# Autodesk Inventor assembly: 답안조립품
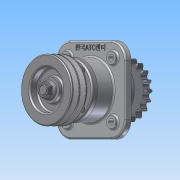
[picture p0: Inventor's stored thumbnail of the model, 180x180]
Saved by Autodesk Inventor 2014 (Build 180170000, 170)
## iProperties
Created: 2015-09
Part Number: 답안조립품
Document SubType Name: Assembly
Designer: study
Author: study
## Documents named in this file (12)
- C:\Users\study\Desktop\450909V1009\답안조립품.iam
- C:\Users\study\Desktop\450909V1009\1-본체.ipt
- C:\Users\study\Desktop\450909V1009\2-커버.ipt
- C:\Users\study\Desktop\450909V1009\6-베어링 6206.ipt
- C:\Users\study\Desktop\450909V1009\8-오일실 30x42.ipt
- C:\Users\study\Desktop\450909V1009\3-축.ipt
- C:\Users\study\Desktop\450909V1009\11-키 6x6.ipt
- C:\Users\study\Desktop\450909V1009\4-V벨트풀리.ipt
- C:\Users\study\Desktop\450909V1009\5-체인 스프로킷.ipt
- C:\Users\study\Desktop\450909V1009\9-M16-너트.ipt
- C:\Users\study\Desktop\450909V1009\7-부시.ipt
- C:\Users\study\Desktop\450909V1009\10-M6.ipt
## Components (23 placed, 11 different names)
1. 1-본체:1
2. 2-커버:1
3. 2-커버:2
4. 6-베어링 6206:1
5. 6-베어링 6206:2
6. 8-8-오일실 30x42:1
7. 8-8-오일실 30x42:2
8. 3-축:1 — 각도:1, 각도:2
9. 11-키 6x6:1 — 각도:1, 각도:3
10. 11-키 6x6:2 — 각도:2, 각도:4
11. 4-V벨트풀리:1 — 각도:3
12. 5-체인 스프로킷:1 — 각도:4
13. 9-M16 너트:1
14. 9-M16 너트:2
15. 7-부시:1
16. 10-M6:2
17. 10-M6:3
18. 10-M6:4
19. 10-M6:5
20. 10-M6:1
21. 10-M6:6
22. 10-M6:7
23. 10-M6:8
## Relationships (4: Angle 4)
- 각도:1 [Angle]: 3-축:1 ↔ 11-키 6x6:1
- 각도:2 [Angle]: 3-축:1 ↔ 11-키 6x6:2
- 각도:3 [Angle]: 11-키 6x6:1 ↔ 4-V벨트풀리:1
- 각도:4 [Angle]: 11-키 6x6:2 ↔ 5-체인 스프로킷:1
